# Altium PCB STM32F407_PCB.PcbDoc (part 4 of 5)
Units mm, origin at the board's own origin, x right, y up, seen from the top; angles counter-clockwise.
Board outline 100.27 x 100.27 mm, 2 copper layers (Top Layer, Bottom Layer); 134 components, 132 nets, 659 pads, 288 vias.
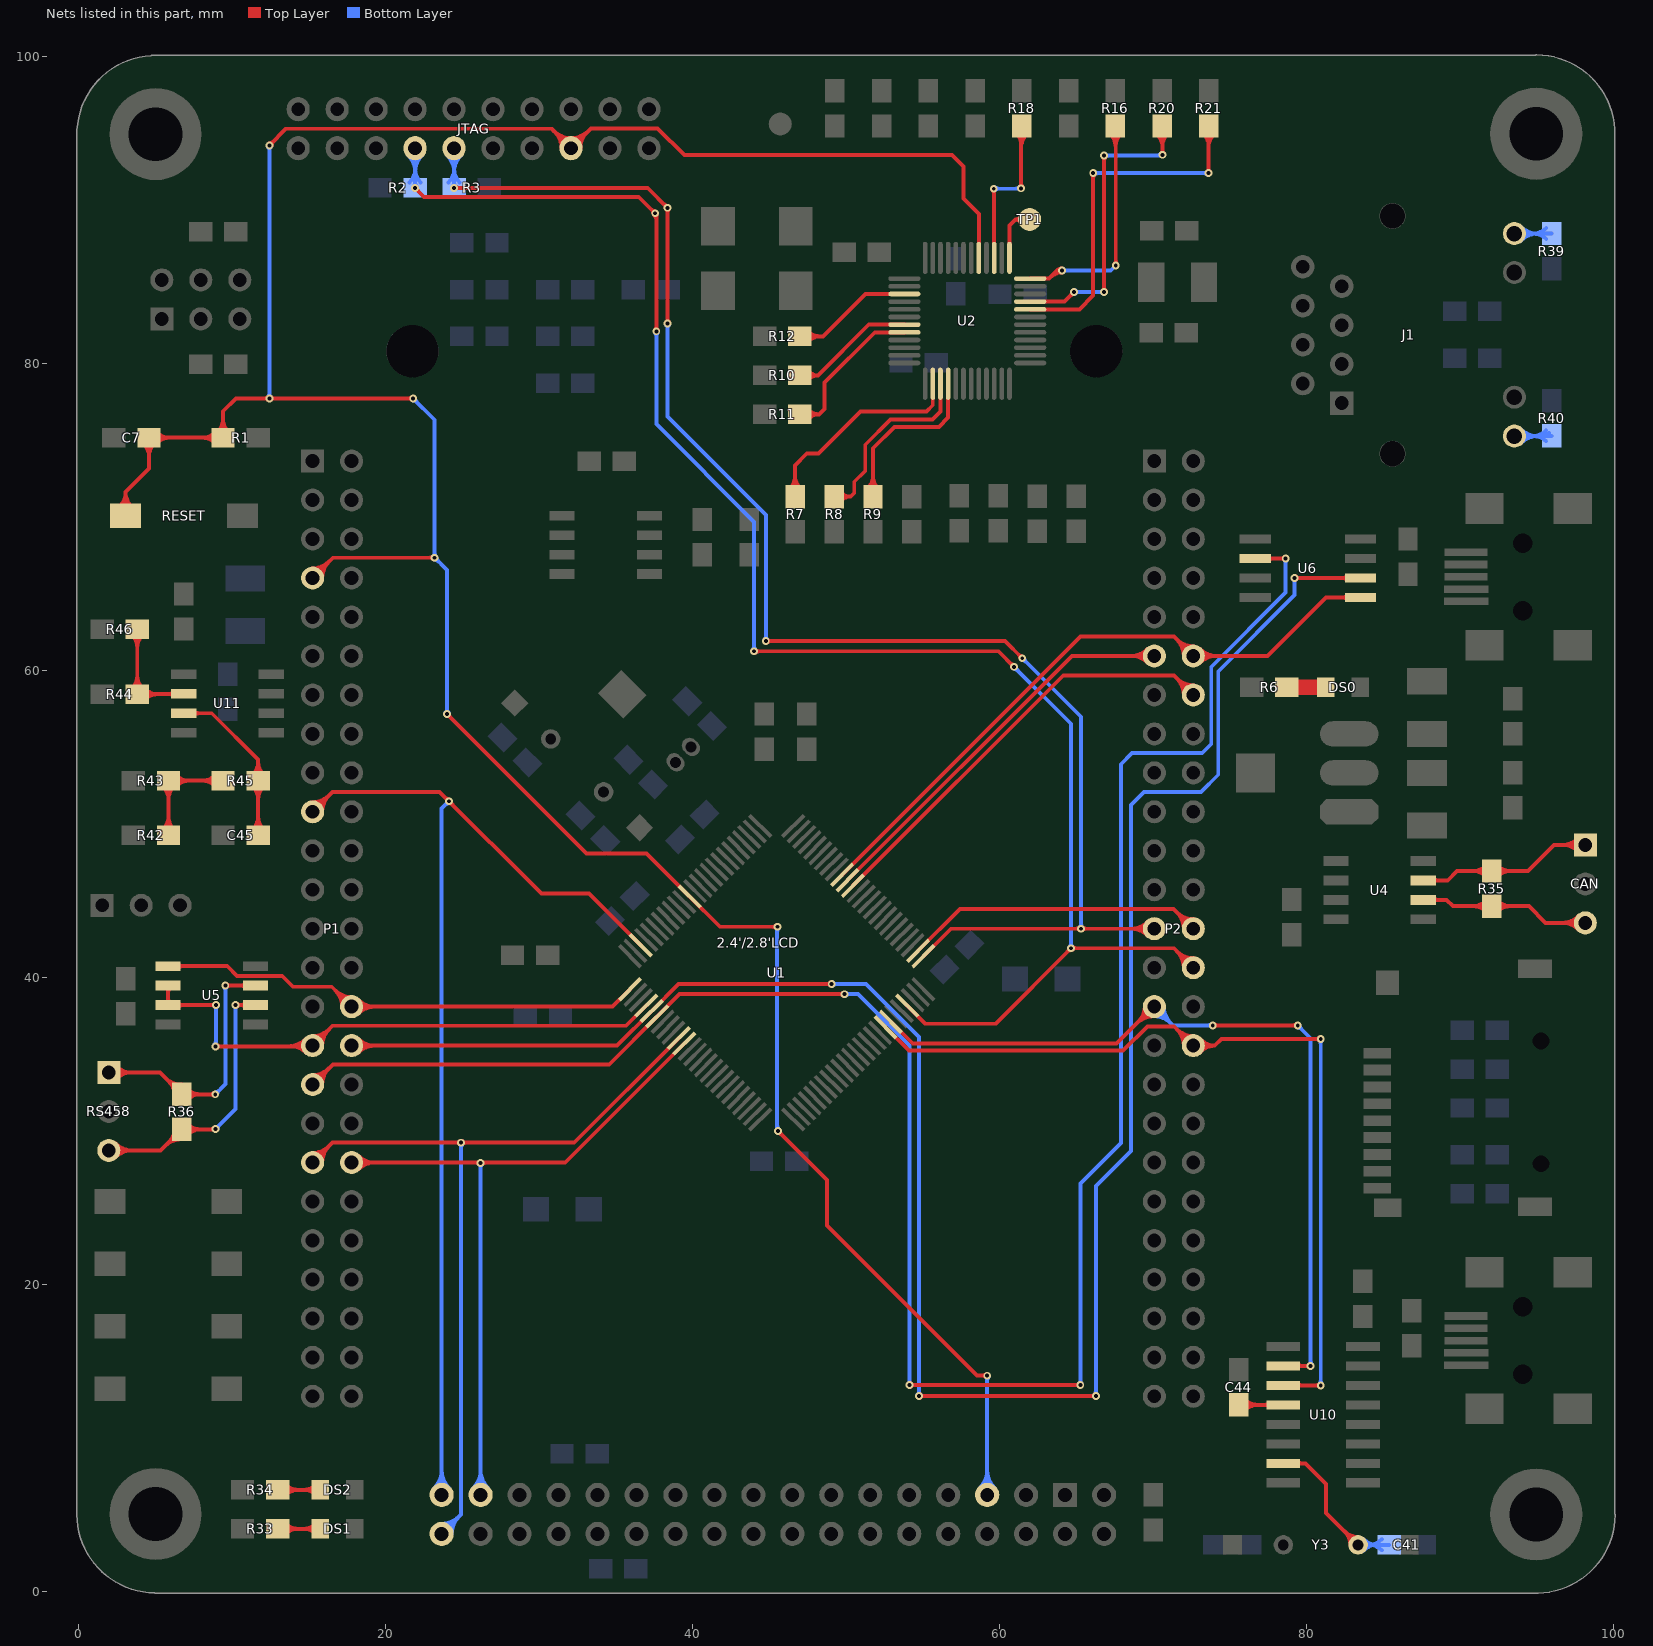
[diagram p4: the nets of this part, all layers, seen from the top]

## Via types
v1: diameter 0.508, hole 0.254, Top Layer to Bottom Layer, 288 vias

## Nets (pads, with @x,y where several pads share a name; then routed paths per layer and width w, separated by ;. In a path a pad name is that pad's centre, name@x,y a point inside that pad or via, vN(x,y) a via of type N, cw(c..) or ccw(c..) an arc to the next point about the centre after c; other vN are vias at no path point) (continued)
NetC41_1: C41.1 U10.7 Y3.1 | length 23.1
  Top Layer w0.254: U10.7@78.502,8.331 79.959,8.331 81.305,6.985 81.305,5.105 Y3.1@83.388,3.023 ; 79.72,8.331 cw(c79.72,8.749) 79.425,8.454 ccw(c79.72,8.749) 79.72,8.331 ; 79.72,8.331 ccw(c79.72,7.914) 79.425,8.209 cw(c79.72,7.914) 79.72,8.331 ; 82.521,3.89 cw(c81.654,3.023) 82.88,3.023 ccw(c81.654,3.023) 82.521,3.89 ; 82.521,3.89 ccw(c83.388,4.757) 83.388,3.531 cw(c83.388,4.757) 82.521,3.89
  Bottom Layer w0.254: Y3.1@83.388,3.023 C41.1@85.419,3.023 ; 84.615,3.023 cw(c84.615,4.249) 83.747,3.382 ccw(c84.615,4.249) 84.615,3.023 ; 84.615,3.023 ccw(c84.615,1.796) 83.747,2.663 cw(c84.615,1.796) 84.615,3.023 ; 84.063,3.023 ccw(c84.063,4.255) 84.934,3.383 cw(c84.063,4.255) 84.063,3.023 ; 84.071,3.023 cw(c84.071,1.802) 84.934,2.665 ccw(c84.071,1.802) 84.071,3.023
NetC44_1: C44.1 U10.4 | length 8
  Top Layer w0.254: C44.1@75.617,12.141 U10.4@78.502,12.141 ; 76.844,12.141 cw(c76.844,13.368) 75.977,12.5 ccw(c76.844,13.368) 76.844,12.141 ; 76.844,12.141 ccw(c76.844,10.915) 75.977,11.782 cw(c76.844,10.915) 76.844,12.141 ; 77.285,12.141 cw(c77.285,11.724) 77.58,12.019 ccw(c77.285,11.724) 77.285,12.141 ; 77.285,12.141 ccw(c77.285,12.559) 77.58,12.264 cw(c77.285,12.559) 77.285,12.141
NetC45_1: C45.1 R45.1 U11.3 | length 24
  Top Layer w0.254: U11.3@6.833,57.226 8.661,57.226 11.684,54.204 R45.1@11.684,52.834 C45.1@11.684,49.278 ; 7.801,57.226 cw(c7.801,57.686) 7.475,57.361 ccw(c7.801,57.686) 7.801,57.226 ; 7.801,57.226 ccw(c7.801,56.766) 7.475,57.091 cw(c7.801,56.766) 7.801,57.226 ; 11.684,50.504 cw(c10.458,50.504) 11.325,49.637 ccw(c10.458,50.504) 11.684,50.504 ; 11.684,50.504 ccw(c12.91,50.504) 12.043,49.637 cw(c12.91,50.504) 11.684,50.504 ; 11.684,51.607 cw(c12.91,51.607) 12.043,52.474 ccw(c12.91,51.607) 11.684,51.607 ; 11.684,51.607 ccw(c10.458,51.607) 11.325,52.474 cw(c10.458,51.607) 11.684,51.607 ; 11.684,54.06 cw(c10.458,54.06) 11.325,53.193 ccw(c10.458,54.06) 11.684,54.06 ; 11.684,54.06 ccw(c12.91,54.06) 12.043,53.193 cw(c12.91,54.06) 11.684,54.06
NetCAN_1: CAN.1 R35.1 U4.7 | length 28.2
  Top Layer w0.254: U4.7@87.64,46.33 89.23,46.33 89.84,46.939 R35.1@92.099,46.939 94.463,46.939 96.164,48.641 CAN.1@98.196,48.641 ; 88.608,46.33 cw(c88.608,46.79) 88.283,46.464 ccw(c88.608,46.79) 88.608,46.33 ; 88.608,46.33 ccw(c88.608,45.87) 88.283,46.195 cw(c88.608,45.87) 88.608,46.33 ; 90.872,46.939 cw(c90.872,45.713) 91.74,46.58 ccw(c90.872,45.713) 90.872,46.939 ; 90.872,46.939 ccw(c90.872,48.166) 91.74,47.298 cw(c90.872,48.166) 90.872,46.939 ; 93.325,46.939 cw(c93.325,48.166) 92.458,47.298 ccw(c93.325,48.166) 93.325,46.939 ; 93.325,46.939 ccw(c93.325,45.713) 92.458,46.58 cw(c93.325,45.713) 93.325,46.939 ; 96.692,48.641 cw(c96.692,47.137) 97.756,48.2 ccw(c96.692,47.137) 96.692,48.641 ; 96.692,48.641 ccw(c96.692,50.145) 97.756,49.082 cw(c96.692,50.145) 96.692,48.641 ; 97.306,48.641 cw(c97.306,47.75) 97.935,48.38 ccw(c97.306,47.75) 97.306,48.641 ; 97.306,48.641 ccw(c97.306,49.532) 97.935,48.902 cw(c97.306,49.532) 97.306,48.641
NetCAN_3: CAN.3 R35.2 U4.6 | length 27.9
  Top Layer w0.254: U4.6@87.64,45.06 89.154,45.06 89.56,44.653 R35.2@92.099,44.653 94.513,44.653 95.606,43.561 CAN.3@98.196,43.561 ; 88.608,45.06 cw(c88.608,45.52) 88.283,45.194 ccw(c88.608,45.52) 88.608,45.06 ; 88.608,45.06 ccw(c88.608,44.6) 88.283,44.925 cw(c88.608,44.6) 88.608,45.06 ; 90.872,44.653 cw(c90.872,43.427) 91.74,44.294 ccw(c90.872,43.427) 90.872,44.653 ; 90.872,44.653 ccw(c90.872,45.88) 91.74,45.012 cw(c90.872,45.88) 90.872,44.653 ; 93.325,44.653 cw(c93.325,45.88) 92.458,45.012 ccw(c93.325,45.88) 93.325,44.653 ; 93.325,44.653 ccw(c93.325,43.427) 92.458,44.294 cw(c93.325,43.427) 93.325,44.653 ; 96.692,43.561 cw(c96.692,42.057) 97.756,43.12 ccw(c96.692,42.057) 96.692,43.561 ; 96.692,43.561 ccw(c96.692,45.065) 97.756,44.002 cw(c96.692,45.065) 96.692,43.561 ; 97.306,43.561 cw(c97.306,42.67) 97.935,43.3 ccw(c97.306,42.67) 97.306,43.561 ; 97.306,43.561 ccw(c97.306,44.452) 97.935,43.822 cw(c97.306,44.452) 97.306,43.561
NetDS0_1: DS0.1 R6.1 | length 2.5
  Top Layer w1.016: R6.1@78.74,58.93 DS0.1@81.278,58.93
NetDS1_1: DS1.1 R33.2 | length 10
  Top Layer w0.254: R33.2@12.954,4.062 DS1.1@15.746,4.062 ; 14.307,4.062 cw(c14.307,5.289) 13.44,4.422 ccw(c14.307,5.289) 14.307,4.062 ; 14.307,4.062 ccw(c14.307,2.836) 13.44,3.703 cw(c14.307,2.836) 14.307,4.062 ; 14.671,4.062 ccw(c14.671,5.141) 15.434,4.378 cw(c14.671,5.141) 14.671,4.062 ; 14.679,4.062 cw(c14.679,2.995) 15.434,3.75 ccw(c14.679,2.995) 14.679,4.062
NetDS2_1: DS2.1 R34.2 | length 10
  Top Layer w0.254: R34.2@12.954,6.602 DS2.1@15.746,6.602 ; 14.307,6.602 cw(c14.307,7.829) 13.44,6.962 ccw(c14.307,7.829) 14.307,6.602 ; 14.307,6.602 ccw(c14.307,5.376) 13.44,6.243 cw(c14.307,5.376) 14.307,6.602 ; 14.671,6.602 ccw(c14.671,7.681) 15.434,6.918 cw(c14.671,7.681) 14.671,6.602 ; 14.679,6.602 cw(c14.679,5.535) 15.434,6.29 ccw(c14.679,5.535) 14.679,6.602
NetJ1_9: J1.9 R40.1 | length 14.9
  Bottom Layer w0.254: J1.9@93.571,75.29 R40.1@95.989,75.29 ; 94.462,75.29 cw(c94.462,76.18) 93.832,75.551 ccw(c94.462,76.18) 94.462,75.29 ; 94.462,75.29 ccw(c94.462,74.399) 93.832,75.029 cw(c94.462,74.399) 94.462,75.29 ; 95.075,75.29 cw(c95.075,76.794) 94.012,75.73 ccw(c95.075,76.794) 95.075,75.29 ; 95.075,75.29 ccw(c95.075,73.786) 94.012,74.849 cw(c95.075,73.786) 95.075,75.29 ; 94.732,75.29 ccw(c94.732,76.589) 95.651,75.67 cw(c94.732,76.589) 94.732,75.29 ; 94.836,75.29 cw(c94.836,74.136) 95.651,74.952 ccw(c94.836,74.136) 94.836,75.29 ; 95.346,75.29 ccw(c95.346,75.976) 95.831,75.491 cw(c95.346,75.976) 95.346,75.29
NetJ1_12: J1.12 R39.2 | length 13.8
  Bottom Layer w0.254: J1.12@93.571,88.49 R39.2@96.006,88.49 ; 94.462,88.49 cw(c94.462,89.38) 93.832,88.751 ccw(c94.462,89.38) 94.462,88.49 ; 94.462,88.49 ccw(c94.462,87.599) 93.832,88.229 cw(c94.462,87.599) 94.462,88.49 ; 95.075,88.49 cw(c95.075,89.994) 94.012,88.93 ccw(c95.075,89.994) 95.075,88.49 ; 95.075,88.49 ccw(c95.075,86.986) 94.012,88.049 cw(c95.075,86.986) 95.075,88.49 ; 94.774,88.49 ccw(c94.774,89.73) 95.651,88.853 cw(c94.774,89.73) 94.774,88.49 ; 94.794,88.49 cw(c94.794,87.277) 95.651,88.134 ccw(c94.794,87.277) 94.794,88.49
NetR7_2: R7.2 U2.2 | length 17.9
  Top Layer w0.254: R7.2@46.685,71.349 46.685,73.383 47.444,74.143 48.209,74.143 50.952,76.886 55.245,76.886 55.662,77.303 U2.2@55.662,78.704 ; 46.685,72.702 cw(c45.459,72.702) 46.326,71.835 ccw(c45.459,72.702) 46.685,72.702 ; 46.685,72.702 ccw(c47.912,72.702) 47.044,71.835 cw(c47.912,72.702) 46.685,72.702
NetR8_2: R8.2 U2.3 | length 15.7
  Top Layer w0.254: R8.2@49.225,71.349 50.317,71.349 ; U2.3@56.162,78.704 56.162,76.888 55.651,76.378 52.908,76.378 51.257,74.727 51.257,73.025 50.546,72.314 50.546,71.577 50.317,71.349 ; 50.317,71.349 cw(c50.317,72.269) 49.614,71.676 ccw(c50.317,72.269) 50.317,71.349 ; 50.317,71.349 ccw(c50.317,70.429) 49.614,71.021 cw(c50.317,70.429) 50.317,71.349
NetR9_2: R9.2 U2.4 | length 14.9
  Top Layer w0.254: R9.2@51.765,71.349 51.765,74.498 53.162,75.895 56.058,75.895 56.662,76.499 U2.4@56.662,78.704 ; 51.765,72.702 cw(c50.539,72.702) 51.406,71.835 ccw(c50.539,72.702) 51.765,72.702 ; 51.765,72.702 ccw(c52.992,72.702) 52.124,71.835 cw(c52.992,72.702) 51.765,72.702
NetR10_2: R10.2 U2.43 | length 11.3
  Top Layer w0.254: R10.2@46.99,79.246 48.182,79.246 ; U2.43@53.812,82.554 51.49,82.554 48.182,79.246 ; 48.182,79.246 cw(c48.182,80.109) 47.512,79.566 ccw(c48.182,80.109) 48.182,79.246 ; 48.182,79.246 ccw(c48.182,78.384) 47.512,78.927 cw(c48.182,78.384) 48.182,79.246
NetR11_2: R11.2 U2.44 | length 13.5
  Top Layer w0.254: R11.2@46.99,76.706 48.258,76.706 ; U2.44@53.812,82.054 51.879,82.054 48.616,78.791 48.616,77.064 48.258,76.706 ; 48.258,76.706 cw(c48.258,77.734) 47.494,77.046 ccw(c48.258,77.734) 48.258,76.706 ; 48.258,76.706 ccw(c48.258,75.678) 47.494,76.366 cw(c48.258,75.678) 48.258,76.706
NetR12_2: R12.2 U2.39 | length 11.8
  Top Layer w0.254: R12.2@46.99,81.786 48.512,81.786 51.28,84.554 U2.39@53.812,84.554 ; 48.343,81.786 cw(c48.343,83.013) 47.476,82.146 ccw(c48.343,83.013) 48.343,81.786 ; 48.343,81.786 ccw(c48.343,80.56) 47.476,81.427 cw(c48.343,80.56) 48.343,81.786
NetR16_2: R16.2 U2.24 | length 24.4
  Top Layer w0.254: U2.24@62.012,85.554 63.227,85.554 63.754,86.081 v1(64.084,86.081) ; R16.2@67.564,95.504 67.589,95.479 v1(67.589,86.411) ; 67.589,86.717 cw(c67.283,86.717) 67.5,86.501 ccw(c67.283,86.717) 67.589,86.717 ; 67.589,86.717 ccw(c67.896,86.717) 67.679,86.501 cw(c67.896,86.717) 67.589,86.717 ; 63.304,85.63 cw(c64.084,84.85) 64.084,85.954 ccw(c64.084,84.85) 63.304,85.63 ; 63.737,86.064 cw(c64.084,85.717) 64.084,86.208 ccw(c64.084,85.717) 63.737,86.064 ; R16.2@67.205,95.018 cw(c66.276,94.089) 67.589,94.089 ccw(c66.276,94.089) R16.2@67.205,95.018 ; R16.2@67.384,95.197 cw(c66.889,94.702) 67.589,94.702 ccw(c66.889,94.702) R16.2@67.384,95.197 ; 67.589,94.212 cw(c68.729,94.212) 67.923,95.018 ccw(c68.729,94.212) 67.589,94.212
  Bottom Layer w0.254: v1(64.084,86.081) 67.259,86.081 v1(67.589,86.411) ; 64.391,86.081 cw(c64.391,86.387) 64.174,86.17 ccw(c64.391,86.387) 64.391,86.081 ; 64.391,86.081 ccw(c64.391,85.774) 64.174,85.991 cw(c64.391,85.774) 64.391,86.081
NetR18_1: R18.1 U2.27 | length 18.6
  Top Layer w0.254: v1(59.639,91.415) 59.662,91.392 U2.27@59.662,86.904 ; v1(61.417,91.44) 61.417,95.452 R18.1@61.47,95.504 ; 61.417,91.747 cw(c61.111,91.747) 61.327,91.53 ccw(c61.111,91.747) 61.417,91.747 ; 61.417,91.747 ccw(c61.724,91.747) 61.507,91.53 cw(c61.724,91.747) 61.417,91.747 ; v1@59.549,91.325 cw(c59.278,91.053) 59.662,91.053 ccw(c59.278,91.053) v1@59.549,91.325 ; R18.1@61.11,95.018 cw(c60.37,94.277) 61.417,94.277 ccw(c60.37,94.277) R18.1@61.11,95.018 ; 61.417,94.024 cw(c62.823,94.024) 61.829,95.018 ccw(c62.823,94.024) 61.417,94.024 ; 61.417,94.637 cw(c62.209,94.637) 61.649,95.197 ccw(c62.209,94.637) 61.417,94.637
  Bottom Layer w0.254: v1(59.639,91.415) 61.392,91.415 v1(61.417,91.44) ; 59.946,91.415 cw(c59.946,91.721) 59.729,91.504 ccw(c59.946,91.721) 59.946,91.415 ; 59.946,91.415 ccw(c59.946,91.108) 59.729,91.325 cw(c59.946,91.108) 59.946,91.415 ; 61.049,91.415 ccw(c61.049,91.808) 61.327,91.53 cw(c61.049,91.808) 61.049,91.415
NetR20_2: R20.2 U2.21 | length 32.1
  Top Layer w0.254: U2.21@62.012,84.054 64.242,84.054 v1(64.872,84.684) ; v1(66.827,84.684) v1(66.827,93.574) ; R20.2@70.612,95.504 70.637,95.479 v1(70.637,93.624) ; 64.655,84.467 cw(c64.872,84.25) 64.872,84.557 ccw(c64.872,84.25) 64.655,84.467 ; 64.655,84.467 ccw(c64.438,84.684) 64.745,84.684 cw(c64.438,84.684) 64.655,84.467 ; 66.827,84.99 cw(c66.521,84.99) 66.738,84.773 ccw(c66.521,84.99) 66.827,84.99 ; 66.827,84.99 ccw(c67.134,84.99) 66.917,84.773 cw(c67.134,84.99) 66.827,84.99 ; 66.827,93.267 cw(c67.134,93.267) 66.917,93.484 ccw(c67.134,93.267) 66.827,93.267 ; 66.827,93.267 ccw(c66.521,93.267) 66.738,93.484 cw(c66.521,93.267) 66.827,93.267 ; 70.637,93.931 cw(c70.331,93.931) 70.548,93.714 ccw(c70.331,93.931) 70.637,93.931 ; 70.637,93.931 ccw(c70.944,93.931) 70.727,93.714 cw(c70.944,93.931) 70.637,93.931 ; R20.2@70.253,95.018 cw(c69.324,94.089) 70.637,94.089 ccw(c69.324,94.089) R20.2@70.253,95.018 ; R20.2@70.432,95.197 cw(c69.937,94.702) 70.637,94.702 ccw(c69.937,94.702) R20.2@70.432,95.197 ; 70.637,94.212 cw(c71.777,94.212) 70.971,95.018 ccw(c71.777,94.212) 70.637,94.212
  Bottom Layer w0.254: v1(64.872,84.684) v1(66.827,84.684) ; v1(66.827,93.574) 70.587,93.574 v1(70.637,93.624) ; 65.178,84.684 cw(c65.178,84.99) 64.961,84.773 ccw(c65.178,84.99) 65.178,84.684 ; 65.178,84.684 ccw(c65.178,84.377) 64.961,84.594 cw(c65.178,84.377) 65.178,84.684 ; 66.521,84.684 cw(c66.521,84.377) 66.738,84.594 ccw(c66.521,84.377) 66.521,84.684 ; 66.521,84.684 ccw(c66.521,84.99) 66.738,84.773 cw(c66.521,84.99) 66.521,84.684 ; 67.134,93.574 cw(c67.134,93.88) 66.917,93.663 ccw(c67.134,93.88) 67.134,93.574 ; 67.134,93.574 ccw(c67.134,93.267) 66.917,93.484 cw(c67.134,93.267) 67.134,93.574 ; 70.208,93.574 ccw(c70.208,94.054) 70.548,93.714 cw(c70.208,94.054) 70.208,93.574
NetR21_2: R21.2 U2.20 | length 31.9
  Top Layer w0.254: U2.20@62.012,83.554 65.215,83.554 66.116,84.455 v1(66.116,92.431) ; v1(73.635,92.431) 73.635,95.479 R21.2@73.66,95.504 ; 66.116,92.124 cw(c66.423,92.124) 66.206,92.341 ccw(c66.423,92.124) 66.116,92.124 ; 66.116,92.124 ccw(c65.81,92.124) 66.026,92.341 cw(c65.81,92.124) 66.116,92.124 ; 73.635,92.737 cw(c73.328,92.737) 73.545,92.52 ccw(c73.328,92.737) 73.635,92.737 ; 73.635,92.737 ccw(c73.941,92.737) 73.724,92.52 cw(c73.941,92.737) 73.635,92.737 ; R21.2@73.301,95.018 cw(c72.495,94.212) 73.635,94.212 ccw(c72.495,94.212) R21.2@73.301,95.018 ; 73.635,94.089 cw(c74.948,94.089) 74.019,95.018 ccw(c74.948,94.089) 73.635,94.089 ; 73.635,94.702 cw(c74.335,94.702) 73.84,95.197 ccw(c74.335,94.702) 73.635,94.702
  Bottom Layer w0.254: v1(66.116,92.431) v1(73.635,92.431) ; 66.423,92.431 cw(c66.423,92.737) 66.206,92.52 ccw(c66.423,92.737) 66.423,92.431 ; 66.423,92.431 ccw(c66.423,92.124) 66.206,92.341 cw(c66.423,92.124) 66.423,92.431 ; 73.328,92.431 cw(c73.328,92.124) 73.545,92.341 ccw(c73.328,92.124) 73.328,92.431 ; 73.328,92.431 ccw(c73.328,92.737) 73.545,92.52 cw(c73.328,92.737) 73.328,92.431
NetR36_1: R36.1 RS458.1 U5.7 | length 38.8
  Top Layer w0.254: RS458.1@1.956,33.807 5.282,33.807 R36.1@6.704,32.385 v1(8.89,32.385) ; v1(9.55,39.472) U5.7@11.517,39.472 ; 2.847,33.807 cw(c2.847,34.698) 2.217,34.068 ccw(c2.847,34.698) 2.847,33.807 ; 2.847,33.807 ccw(c2.847,32.917) 2.217,33.546 cw(c2.847,32.917) 2.847,33.807 ; 3.46,33.807 cw(c3.46,35.311) 2.396,34.248 ccw(c3.46,35.311) 3.46,33.807 ; 3.46,33.807 ccw(c3.46,32.303) 2.396,33.367 cw(c3.46,32.303) 3.46,33.807 ; 7.93,32.385 cw(c7.93,33.611) 7.063,32.744 ccw(c7.93,33.611) 7.93,32.385 ; 7.93,32.385 ccw(c7.93,31.159) 7.063,32.026 cw(c7.93,31.159) 7.93,32.385 ; 8.583,32.385 cw(c8.583,32.078) 8.8,32.295 ccw(c8.583,32.078) 8.583,32.385 ; 8.583,32.385 ccw(c8.583,32.692) 8.8,32.475 cw(c8.583,32.692) 8.583,32.385 ; 9.857,39.472 cw(c9.857,39.778) 9.64,39.561 ccw(c9.857,39.778) 9.857,39.472 ; 9.857,39.472 ccw(c9.857,39.165) 9.64,39.382 cw(c9.857,39.165) 9.857,39.472 ; 10.549,39.472 cw(c10.549,39.012) 10.874,39.337 ccw(c10.549,39.012) 10.549,39.472 ; 10.549,39.472 ccw(c10.549,39.932) 10.874,39.606 cw(c10.549,39.932) 10.549,39.472 ; 5.62,33.469 ccw(c6.704,34.553) 6.704,33.02 cw(c6.704,34.553) 5.62,33.469 ; 5.927,33.162 cw(c5.276,32.512) 6.196,32.512 ccw(c5.276,32.512) 5.927,33.162 ; 6.054,33.035 ccw(c6.704,33.686) 6.704,32.766 cw(c6.704,33.686) 6.054,33.035
  Bottom Layer w0.254: v1(8.89,32.385) 9.55,33.045 v1(9.55,39.472) ; 9.107,32.602 cw(c8.89,32.819) 8.89,32.512 ccw(c8.89,32.819) 9.107,32.602 ; 9.107,32.602 ccw(c9.324,32.385) 9.017,32.385 cw(c9.324,32.385) 9.107,32.602 ; 9.55,39.165 cw(c9.857,39.165) 9.64,39.382 ccw(c9.857,39.165) 9.55,39.165 ; 9.55,39.165 ccw(c9.244,39.165) 9.461,39.382 cw(c9.244,39.165) 9.55,39.165
NetR36_2: R36.2 RS458.3 U5.6 | length 39.1
  Top Layer w0.254: RS458.3@1.956,28.727 5.332,28.727 R36.2@6.704,30.099 8.89,30.099 v1(8.915,30.124) ; v1(10.211,38.202) U5.6@11.517,38.202 ; 2.847,28.727 cw(c2.847,29.618) 2.217,28.988 ccw(c2.847,29.618) 2.847,28.727 ; 2.847,28.727 ccw(c2.847,27.837) 2.217,28.466 cw(c2.847,27.837) 2.847,28.727 ; 3.46,28.727 cw(c3.46,30.231) 2.396,29.168 ccw(c3.46,30.231) 3.46,28.727 ; 3.46,28.727 ccw(c3.46,27.223) 2.396,28.287 cw(c3.46,27.223) 3.46,28.727 ; 7.93,30.099 cw(c7.93,31.325) 7.063,30.458 ccw(c7.93,31.325) 7.93,30.099 ; 7.93,30.099 ccw(c7.93,28.873) 7.063,29.74 cw(c7.93,28.873) 7.93,30.099 ; 10.517,38.202 cw(c10.517,38.508) 10.301,38.291 ccw(c10.517,38.508) 10.517,38.202 ; 10.517,38.202 ccw(c10.517,37.895) 10.301,38.112 cw(c10.517,37.895) 10.517,38.202 ; 10.549,38.202 cw(c10.549,37.742) 10.874,38.067 ccw(c10.549,37.742) 10.549,38.202 ; 10.549,38.202 ccw(c10.549,38.662) 10.874,38.336 cw(c10.549,38.662) 10.549,38.202 ; 5.62,29.015 cw(c6.704,27.931) 6.704,29.464 ccw(c6.704,27.931) 5.62,29.015 ; 5.927,29.322 ccw(c5.276,29.972) 6.196,29.972 cw(c5.276,29.972) 5.927,29.322 ; 6.054,29.449 cw(c6.704,28.798) 6.704,29.718 ccw(c6.704,28.798) 6.054,29.449 ; 8.547,30.099 ccw(c8.547,30.492) 8.826,30.214 cw(c8.547,30.492) 8.547,30.099
  Bottom Layer w0.254: v1(8.915,30.124) 10.211,31.42 v1(10.211,38.202) ; 9.132,30.341 cw(c8.915,30.558) 8.915,30.251 ccw(c8.915,30.558) 9.132,30.341 ; 9.132,30.341 ccw(c9.349,30.124) 9.042,30.124 cw(c9.349,30.124) 9.132,30.341 ; 10.211,37.895 cw(c10.517,37.895) 10.301,38.112 ccw(c10.517,37.895) 10.211,37.895 ; 10.211,37.895 ccw(c9.904,37.895) 10.121,38.112 cw(c9.904,37.895) 10.211,37.895
NetR42_2: R42.2 R43.2 R45.2 | length 22.5
  Top Layer w0.254: R42.2@5.842,49.274 R43.2@5.842,52.83 R45.2@9.395,52.83 ; 5.842,50.501 cw(c4.616,50.501) 5.483,49.634 ccw(c4.616,50.501) 5.842,50.501 ; 5.842,50.501 ccw(c7.068,50.501) 6.201,49.634 cw(c7.068,50.501) 5.842,50.501 ; 5.842,51.604 cw(c7.068,51.604) 6.201,52.471 ccw(c7.068,51.604) 5.842,51.604 ; 5.842,51.604 ccw(c4.616,51.604) 5.483,52.471 cw(c4.616,51.604) 5.842,51.604 ; 7.195,52.83 cw(c7.195,54.057) 6.328,53.19 ccw(c7.195,54.057) 7.195,52.83 ; 7.195,52.83 ccw(c7.195,51.604) 6.328,52.471 cw(c7.195,51.604) 7.195,52.83 ; 8.037,52.83 ccw(c8.037,54.068) 8.912,53.193 cw(c8.037,54.068) 8.037,52.83 ; 8.052,52.83 cw(c8.052,51.615) 8.912,52.474 ccw(c8.052,51.615) 8.052,52.83
NetR44_2: R44.2 R46.2 U11.2 | length 20.2
  Top Layer w0.254: R46.2@3.81,62.711 R44.2@3.81,58.469 U11.2@6.806,58.469 ; 3.81,59.696 cw(c2.584,59.696) 3.451,58.828 ccw(c2.584,59.696) 3.81,59.696 ; 3.81,59.696 ccw(c5.036,59.696) 4.169,58.828 cw(c5.036,59.696) 3.81,59.696 ; 3.81,61.485 cw(c5.036,61.485) 4.169,62.352 ccw(c5.036,61.485) 3.81,61.485 ; 3.81,61.485 ccw(c2.584,61.485) 3.451,62.352 cw(c2.584,61.485) 3.81,61.485 ; 5.163,58.469 cw(c5.163,59.696) 4.296,58.828 ccw(c5.163,59.696) 5.163,58.469 ; 5.163,58.469 ccw(c5.163,57.243) 4.296,58.11 cw(c5.163,57.243) 5.163,58.469 ; 5.799,58.469 ccw(c5.799,59.021) 6.19,58.631 cw(c5.799,59.021) 5.799,58.469 ; 5.93,58.469 cw(c5.93,58.102) 6.19,58.361 ccw(c5.93,58.102) 5.93,58.469
NetTP1_1: TP1.1 U2.25 | length 5.3
  Top Layer w0.254: U2.25@60.662,86.904 60.662,89.008 61.062,89.408 ; TP1.1@61.976,89.408 61.062,89.408 ; 61.062,89.408 cw(c61.062,89.049) 61.396,89.18 ccw(c61.062,89.049) 61.062,89.408 ; 61.062,89.408 ccw(c61.062,89.767) 61.396,89.636 cw(c61.062,89.767) 61.062,89.408
NRST: 2.4'/2.8'LCD.5 C7.1 JTAG.15 P1.7 R1.2 RESET.1 U1.14 U2.29 | length 266.6
  Top Layer w0.254: RESET.1@3.048,70.104 3.048,71.653 ; v1(12.421,94.234) 13.513,95.326 30.81,95.326 JTAG.15@32.08,94.056 33.376,95.352 37.719,95.352 39.472,93.599 56.921,93.599 57.658,92.862 57.658,90.78 58.662,89.776 U2.29@58.662,86.904 ; P1.7@15.24,66.04 16.561,67.361 v1(23.19,67.361) ; v1(21.793,77.749) v1(12.421,77.749) 10.236,77.749 9.398,76.911 R1.2@9.398,75.186 C7.1@4.572,75.186 4.572,73.177 3.048,71.653 ; v1(24.003,57.175) 33.096,48.082 37.012,48.082 U1.14@39.817,45.277 41.787,43.307 v1(45.542,43.307) ; v1(45.568,29.997) 48.768,26.797 48.768,23.825 58.547,14.046 v1(59.207,14.046) ; 3.048,71.069 cw(c2.147,71.069) 2.762,70.41 ccw(c2.147,71.069) 3.048,71.069 ; 3.048,71.069 ccw(c3.949,71.069) 3.334,70.41 cw(c3.949,71.069) 3.048,71.069 ; 3.048,71.653 cw(c1.601,71.653) 2.589,70.596 ccw(c1.601,71.653) 3.048,71.653 ; 3.048,71.653 ccw(c4.495,71.653) 3.507,70.596 cw(c4.495,71.653) 3.048,71.653 ; 4.572,73.959 cw(c5.798,73.959) 4.931,74.826 ccw(c5.798,73.959) 4.572,73.959 ; 4.572,73.959 ccw(c3.346,73.959) 4.213,74.826 cw(c3.346,73.959) 4.572,73.959 ; 5.925,75.186 cw(c5.925,76.412) 5.058,75.545 ccw(c5.925,76.412) 5.925,75.186 ; 5.925,75.186 ccw(c5.925,73.959) 5.058,74.826 cw(c5.925,73.959) 5.925,75.186 ; 8.045,75.186 cw(c8.045,73.959) 8.912,74.826 ccw(c8.045,73.959) 8.045,75.186 ; 8.045,75.186 ccw(c8.045,76.412) 8.912,75.545 cw(c8.045,76.412) 8.045,75.186 ; 9.398,76.412 cw(c8.172,76.412) 9.039,75.545 ccw(c8.172,76.412) 9.398,76.412 ; 9.398,76.412 ccw(c10.624,76.412) 9.757,75.545 cw(c10.624,76.412) 9.398,76.412 ; 12.114,77.749 cw(c12.114,77.443) 12.331,77.66 ccw(c12.114,77.443) 12.114,77.749 ; 12.114,77.749 ccw(c12.114,78.056) 12.331,77.839 cw(c12.114,78.056) 12.114,77.749 ; 12.637,94.451 cw(c12.421,94.668) 12.421,94.361 ccw(c12.421,94.668) 12.637,94.451 ; 12.637,94.451 ccw(c12.854,94.234) 12.548,94.234 cw(c12.854,94.234) 12.637,94.451 ; 12.727,77.749 cw(c12.727,78.056) 12.51,77.839 ccw(c12.727,78.056) 12.727,77.749 ; 12.727,77.749 ccw(c12.727,77.443) 12.51,77.66 cw(c12.727,77.443) 12.727,77.749 ; 15.87,66.67 cw(c15.24,67.3) 15.24,66.409 ccw(c15.24,67.3) 15.87,66.67 ; 15.87,66.67 ccw(c16.5,66.04) 15.609,66.04 cw(c16.5,66.04) 15.87,66.67 ; 16.304,67.104 cw(c15.24,68.167) 15.24,66.663 ccw(c15.24,68.167) 16.304,67.104 ; 16.304,67.104 ccw(c17.367,66.04) 15.863,66.04 cw(c17.367,66.04) 16.304,67.104 ; 21.487,77.749 cw(c21.487,77.443) 21.703,77.66 ccw(c21.487,77.443) 21.487,77.749 ; 21.487,77.749 ccw(c21.487,78.056) 21.703,77.839 cw(c21.487,78.056) 21.487,77.749 ; 22.884,67.361 cw(c22.884,67.054) 23.1,67.271 ccw(c22.884,67.054) 22.884,67.361 ; 22.884,67.361 ccw(c22.884,67.667) 23.1,67.451 cw(c22.884,67.667) 22.884,67.361 ; 24.22,56.959 cw(c24.437,57.175) 24.13,57.175 ccw(c24.437,57.175) 24.22,56.959 ; 24.22,56.959 ccw(c24.003,56.742) 24.003,57.048 cw(c24.003,56.742) 24.22,56.959 ; JTAG.15@32.08,94.463 cw(c32.08,95.444) 31.386,94.75 ccw(c32.08,95.444) JTAG.15@32.08,94.463 ; JTAG.15@32.08,94.463 ccw(c32.08,95.444) 32.774,94.75 cw(c32.08,95.444) JTAG.15@32.08,94.463 ; JTAG.15@32.08,94.717 cw(c32.08,96.311) 30.953,95.184 ccw(c32.08,96.311) JTAG.15@32.08,94.717 ; JTAG.15@32.08,94.717 ccw(c32.08,96.311) 33.208,95.184 cw(c32.08,96.311) JTAG.15@32.08,94.717 ; 45.236,43.307 cw(c45.236,43) 45.452,43.217 ccw(c45.236,43) 45.236,43.307 ; 45.236,43.307 ccw(c45.236,43.614) 45.452,43.397 cw(c45.236,43.614) 45.236,43.307 ; 45.784,29.781 cw(c46.001,29.997) 45.695,29.997 ccw(c46.001,29.997) 45.784,29.781 ; 45.784,29.781 ccw(c45.568,29.564) 45.568,29.87 cw(c45.568,29.564) 45.784,29.781 ; 58.901,14.046 cw(c58.901,13.74) 59.118,13.956 ccw(c58.901,13.74) 58.901,14.046 ; 58.901,14.046 ccw(c58.901,14.353) 59.118,14.136 cw(c58.901,14.353) 58.901,14.046 ; 31.043,95.093 cw(c30.043,94.094) 31.457,94.094 ccw(c30.043,94.094) 31.043,95.093 ; 31.477,94.66 cw(c30.911,94.094) 31.711,94.094 ccw(c30.911,94.094) 31.477,94.66 ; JTAG.15@32.449,94.094 cw(c33.25,94.094) 32.684,94.66 ccw(c33.25,94.094) JTAG.15@32.449,94.094 ; JTAG.15@32.703,94.094 cw(c34.117,94.094) 33.117,95.093 ccw(c34.117,94.094) JTAG.15@32.703,94.094
  Bottom Layer w0.254: v1(12.421,77.749) v1(12.421,94.234) ; v1(21.793,77.749) 23.19,76.352 v1(23.19,67.361) ; v1@23.216,67.361 24.003,66.573 v1(24.003,57.175) ; v1@45.517,43.332 45.517,30.048 v1(45.568,29.997) ; 2.4'/2.8'LCD.5@59.207,6.274 v1(59.207,14.046) ; 12.421,78.056 cw(c12.114,78.056) 12.331,77.839 ccw(c12.114,78.056) 12.421,78.056 ; 12.421,78.056 ccw(c12.727,78.056) 12.51,77.839 cw(c12.727,78.056) 12.421,78.056 ; 12.421,93.927 cw(c12.727,93.927) 12.51,94.144 ccw(c12.727,93.927) 12.421,93.927 ; 12.421,93.927 ccw(c12.114,93.927) 12.331,94.144 cw(c12.114,93.927) 12.421,93.927 ; 22.01,77.533 cw(c22.227,77.749) 21.92,77.749 ccw(c22.227,77.749) 22.01,77.533 ; 22.01,77.533 ccw(c21.793,77.316) 21.793,77.622 cw(c21.793,77.316) 22.01,77.533 ; 23.19,67.667 cw(c22.884,67.667) 23.1,67.451 ccw(c22.884,67.667) 23.19,67.667 ; 23.19,67.667 ccw(c23.497,67.667) 23.28,67.451 cw(c23.497,67.667) 23.19,67.667 ; 24.003,57.482 cw(c23.696,57.482) 23.913,57.265 ccw(c23.696,57.482) 24.003,57.482 ; 24.003,57.482 ccw(c24.31,57.482) 24.093,57.265 cw(c24.31,57.482) 24.003,57.482 ; 59.207,7.255 cw(c58.226,7.255) 58.92,6.561 ccw(c58.226,7.255) 59.207,7.255 ; 59.207,7.255 ccw(c60.189,7.255) 59.495,6.561 cw(c60.189,7.255) 59.207,7.255 ; 59.207,7.868 cw(c57.613,7.868) 58.74,6.741 ccw(c57.613,7.868) 59.207,7.868 ; 59.207,7.868 ccw(c60.802,7.868) 59.674,6.741 cw(c60.802,7.868) 59.207,7.868 ; 59.207,13.74 cw(c59.514,13.74) 59.297,13.956 ccw(c59.514,13.74) 59.207,13.74 ; 59.207,13.74 ccw(c58.901,13.74) 59.118,13.956 cw(c58.901,13.74) 59.207,13.74 ; v1@23.19,67.234 cw(c23.19,66.866) 23.45,67.126 ccw(c23.19,66.866) v1@23.19,67.234 ; v1@23.317,67.361 ccw(c23.562,67.361) 23.389,67.187 cw(c23.562,67.361) v1@23.317,67.361 ; 45.517,30.427 ccw(c45.997,30.427) 45.657,30.087 cw(c45.997,30.427) 45.517,30.427 ; 45.517,42.939 cw(c45.91,42.939) 45.632,43.217 ccw(c45.91,42.939) 45.517,42.939
PA0: 2.4'/2.8'LCD.33 P1.19 U1.23 | length 90
  Top Layer w0.254: P1.19@15.24,50.8 16.535,52.095 23.52,52.095 30.15,45.466 33.264,45.466 U1.23@36.635,42.095 ; 15.87,51.43 cw(c15.24,52.06) 15.24,51.169 ccw(c15.24,52.06) 15.87,51.43 ; 15.87,51.43 ccw(c16.5,50.8) 15.609,50.8 cw(c16.5,50.8) 15.87,51.43 ; 16.304,51.864 cw(c15.24,52.927) 15.24,51.423 ccw(c15.24,52.927) 16.304,51.864 ; 16.304,51.864 ccw(c17.367,50.8) 15.863,50.8 cw(c17.367,50.8) 16.304,51.864 ; 23.913,51.703 cw(c23.696,51.486) 24.003,51.486 ccw(c23.696,51.486) 23.913,51.703 ; 23.913,51.703 ccw(c24.13,51.919) 24.13,51.613 cw(c24.13,51.919) 23.913,51.703 ; 24.347,51.269 cw(c24.564,51.486) 24.257,51.486 ccw(c24.564,51.486) 24.347,51.269 ; 24.347,51.269 ccw(c24.13,51.052) 24.13,51.359 cw(c24.13,51.052) 24.347,51.269
  Bottom Layer w0.254: 2.4'/2.8'LCD.33@23.647,6.274 23.647,51.003 v1(24.13,51.486) ; 23.647,7.255 cw(c22.666,7.255) 23.36,6.561 ccw(c22.666,7.255) 23.647,7.255 ; 23.647,7.255 ccw(c24.629,7.255) 23.935,6.561 cw(c24.629,7.255) 23.647,7.255 ; 23.647,7.868 cw(c22.053,7.868) 23.18,6.741 ccw(c22.053,7.868) 23.647,7.868 ; 23.647,7.868 ccw(c25.242,7.868) 24.114,6.741 cw(c25.242,7.868) 23.647,7.868 ; 23.913,51.269 cw(c24.13,51.052) 24.13,51.359 ccw(c24.13,51.052) 23.913,51.269 ; 23.913,51.269 ccw(c23.696,51.486) 24.003,51.486 cw(c23.696,51.486) 23.913,51.269
PA3: P1.30 U1.26 U5.1 | length 48.2
  Top Layer w0.254: U5.1@5.817,40.742 9.677,40.742 10.312,40.107 13.259,40.107 13.97,39.395 16.485,39.395 P1.30@17.78,38.1 34.796,38.1 U1.26@35.928,39.231 ; 6.785,40.742 cw(c6.785,41.202) 6.459,40.876 ccw(c6.785,41.202) 6.785,40.742 ; 6.785,40.742 ccw(c6.785,40.282) 6.459,40.607 cw(c6.785,40.282) 6.785,40.742 ; 16.716,39.164 cw(c15.653,38.1) 17.157,38.1 ccw(c15.653,38.1) 16.716,39.164 ; 16.716,39.164 ccw(c17.78,40.227) 17.78,38.723 cw(c17.78,40.227) 16.716,39.164 ; 17.15,38.73 cw(c16.52,38.1) 17.411,38.1 ccw(c16.52,38.1) 17.15,38.73 ; 17.15,38.73 ccw(c17.78,39.36) 17.78,38.469 cw(c17.78,39.36) 17.15,38.73 ; 18.671,38.1 cw(c18.671,38.991) 18.041,38.361 ccw(c18.671,38.991) 18.671,38.1 ; 18.671,38.1 ccw(c18.671,37.209) 18.041,37.839 cw(c18.671,37.209) 18.671,38.1 ; 19.284,38.1 cw(c19.284,39.604) 18.221,38.541 ccw(c19.284,39.604) 19.284,38.1 ; 19.284,38.1 ccw(c19.284,36.596) 18.221,37.659 cw(c19.284,36.596) 19.284,38.1
PA4: P1.31 U1.29 U5.2 U5.3 | length 59.1
  Top Layer w0.254: U5.2@5.817,39.472 U5.3@5.817,38.202 v1(8.941,38.202) ; v1(8.915,35.509) P1.31@15.189,35.509 ; P1.31@15.24,35.56 16.535,36.855 35.673,36.855 U1.29@36.988,38.171 ; 5.817,38.662 cw(c5.357,38.662) 5.682,38.336 ccw(c5.357,38.662) 5.817,38.662 ; 5.817,38.662 ccw(c6.277,38.662) 5.951,38.336 cw(c6.277,38.662) 5.817,38.662 ; 5.817,39.012 cw(c6.277,39.012) 5.951,39.337 ccw(c6.277,39.012) 5.817,39.012 ; 5.817,39.012 ccw(c5.357,39.012) 5.682,39.337 cw(c5.357,39.012) 5.817,39.012 ; 6.785,38.202 cw(c6.785,38.662) 6.459,38.336 ccw(c6.785,38.662) 6.785,38.202 ; 6.785,38.202 ccw(c6.785,37.742) 6.459,38.067 cw(c6.785,37.742) 6.785,38.202 ; 8.634,38.202 cw(c8.634,37.895) 8.851,38.112 ccw(c8.634,37.895) 8.634,38.202 ; 8.634,38.202 ccw(c8.634,38.508) 8.851,38.291 cw(c8.634,38.508) 8.634,38.202 ; 9.222,35.509 cw(c9.222,35.816) 9.005,35.599 ccw(c9.222,35.816) 9.222,35.509 ; 9.222,35.509 ccw(c9.222,35.203) 9.005,35.419 cw(c9.222,35.203) 9.222,35.509 ; 15.87,36.19 cw(c15.24,36.82) 15.24,35.929 ccw(c15.24,36.82) 15.87,36.19 ; 15.87,36.19 ccw(c16.5,35.56) 15.609,35.56 cw(c16.5,35.56) 15.87,36.19 ; 16.304,36.624 cw(c15.24,37.687) 15.24,36.183 ccw(c15.24,37.687) 16.304,36.624 ; 16.304,36.624 ccw(c17.367,35.56) 15.863,35.56 cw(c17.367,35.56) 16.304,36.624 ; 13.613,35.509 ccw(c13.613,37.187) 14.799,36.001 cw(c13.613,37.187) 13.613,35.509 ; 13.859,35.509 cw(c13.859,34.179) 14.799,35.119 ccw(c13.859,34.179) 13.859,35.509 ; 14.227,35.509 ccw(c14.227,36.573) 14.979,35.821 cw(c14.227,36.573) 14.227,35.509 ; 14.472,35.509 cw(c14.472,34.792) 14.979,35.299 ccw(c14.472,34.792) 14.472,35.509
  Bottom Layer w0.254: v1(8.915,35.509) 8.941,35.535 v1(8.941,38.202) ; 8.941,37.895 cw(c9.247,37.895) 9.031,38.112 ccw(c9.247,37.895) 8.941,37.895 ; 8.941,37.895 ccw(c8.634,37.895) 8.851,38.112 cw(c8.634,37.895) 8.941,37.895 ; v1@8.826,35.599 ccw(c8.547,35.877) 8.941,35.877 cw(c8.547,35.877) v1@8.826,35.599
PA5: P1.32 U1.30 U6.6 | length 156.7
  Top Layer w0.254: P1.32@17.78,35.56 35.085,35.56 U1.30@37.342,37.817 39.098,39.573 v1(49.073,39.573) ; v1(54.762,12.725) v1(66.294,12.725) ; v1(79.248,66.04) U6.6@83.541,66.04 ; 18.671,35.56 cw(c18.671,36.451) 18.041,35.821 ccw(c18.671,36.451) 18.671,35.56 ; 18.671,35.56 ccw(c18.671,34.669) 18.041,35.299 cw(c18.671,34.669) 18.671,35.56 ; 19.284,35.56 cw(c19.284,37.064) 18.221,36.001 ccw(c19.284,37.064) 19.284,35.56 ; 19.284,35.56 ccw(c19.284,34.056) 18.221,35.119 cw(c19.284,34.056) 19.284,35.56 ; 48.766,39.573 cw(c48.766,39.267) 48.983,39.483 ccw(c48.766,39.267) 48.766,39.573 ; 48.766,39.573 ccw(c48.766,39.88) 48.983,39.663 cw(c48.766,39.88) 48.766,39.573 ; 55.069,12.725 cw(c55.069,13.032) 54.852,12.815 ccw(c55.069,13.032) 55.069,12.725 ; 55.069,12.725 ccw(c55.069,12.419) 54.852,12.636 cw(c55.069,12.419) 55.069,12.725 ; 65.987,12.725 cw(c65.987,12.419) 66.204,12.636 ccw(c65.987,12.419) 65.987,12.725 ; 65.987,12.725 ccw(c65.987,13.032) 66.204,12.815 cw(c65.987,13.032) 65.987,12.725 ; 79.555,66.04 cw(c79.555,66.347) 79.338,66.13 ccw(c79.555,66.347) 79.555,66.04 ; 79.555,66.04 ccw(c79.555,65.733) 79.338,65.95 cw(c79.555,65.733) 79.555,66.04 ; 82.4,66.04 cw(c82.4,65.611) 82.704,65.914 ccw(c82.4,65.611) 82.4,66.04 ; 82.4,66.04 ccw(c82.4,66.469) 82.704,66.166 cw(c82.4,66.469) 82.4,66.04
  Bottom Layer w0.254: v1(49.073,39.573) 51.308,39.573 54.762,36.119 v1(54.762,12.725) ; v1(66.294,12.725) 66.294,26.416 68.58,28.702 68.58,51.246 69.43,52.095 73.152,52.095 74.27,53.213 74.27,59.944 79.248,64.922 v1(79.248,66.04) ; 49.379,39.573 cw(c49.379,39.88) 49.163,39.663 ccw(c49.379,39.88) 49.379,39.573 ; 49.379,39.573 ccw(c49.379,39.267) 49.163,39.483 cw(c49.379,39.267) 49.379,39.573 ; 54.762,13.032 cw(c54.456,13.032) 54.673,12.815 ccw(c54.456,13.032) 54.762,13.032 ; 54.762,13.032 ccw(c55.069,13.032) 54.852,12.815 cw(c55.069,13.032) 54.762,13.032 ; 66.294,13.032 cw(c65.987,13.032) 66.204,12.815 ccw(c65.987,13.032) 66.294,13.032 ; 66.294,13.032 ccw(c66.601,13.032) 66.384,12.815 cw(c66.601,13.032) 66.294,13.032 ; 79.248,65.733 cw(c79.555,65.733) 79.338,65.95 ccw(c79.555,65.733) 79.248,65.733 ; 79.248,65.733 ccw(c78.941,65.733) 79.158,65.95 cw(c78.941,65.733) 79.248,65.733
PA6: P1.33 U1.31 U6.2 | length 156.6
  Top Layer w0.254: P1.33@15.24,33.02 16.561,34.341 34.573,34.341 U1.31@37.696,37.464 39.145,38.913 v1@49.886,38.913 ; v1(54.153,13.437) v1(65.278,13.437) ; U6.2@76.683,67.308 78.662,67.308 v1(78.664,67.31) ; 15.87,33.65 cw(c15.24,34.28) 15.24,33.389 ccw(c15.24,34.28) 15.87,33.65 ; 15.87,33.65 ccw(c16.5,33.02) 15.609,33.02 cw(c16.5,33.02) 15.87,33.65 ; 16.304,34.084 cw(c15.24,35.147) 15.24,33.643 ccw(c15.24,35.147) 16.304,34.084 ; 16.304,34.084 ccw(c17.367,33.02) 15.863,33.02 cw(c17.367,33.02) 16.304,34.084 ; 49.604,38.913 cw(c49.604,38.606) 49.821,38.823 ccw(c49.604,38.606) 49.604,38.913 ; 49.604,38.913 ccw(c49.604,39.219) 49.821,39.003 cw(c49.604,39.219) 49.604,38.913 ; 54.459,13.437 cw(c54.459,13.743) 54.243,13.526 ccw(c54.459,13.743) 54.459,13.437 ; 54.459,13.437 ccw(c54.459,13.13) 54.243,13.347 cw(c54.459,13.13) 54.459,13.437 ; 64.971,13.437 cw(c64.971,13.13) 65.188,13.347 ccw(c64.971,13.13) 64.971,13.437 ; 64.971,13.437 ccw(c64.971,13.743) 65.188,13.526 cw(c64.971,13.743) 64.971,13.437 ; 77.823,67.308 cw(c77.823,67.738) 77.52,67.434 ccw(c77.823,67.738) 77.823,67.308 ; 77.823,67.308 ccw(c77.823,66.879) 77.52,67.183 cw(c77.823,66.879) 77.823,67.308 ; 78.353,67.308 ccw(c78.353,67.621) 78.574,67.4 cw(c78.353,67.621) 78.353,67.308 ; 78.361,67.308 cw(c78.361,67.007) 78.574,67.22 ccw(c78.361,67.007) 78.361,67.308
  Bottom Layer w0.254: v1(49.911,38.913) 50.8,38.913 54.153,35.56 v1(54.153,13.437) ; v1(65.278,13.437) 65.278,26.568 67.92,29.21 67.92,53.899 68.656,54.635 73.228,54.635 73.812,55.22 73.812,60.249 78.664,65.1 v1(78.664,67.31) ; 50.218,38.913 cw(c50.218,39.219) 50.001,39.003 ccw(c50.218,39.219) 50.218,38.913 ; 50.218,38.913 ccw(c50.218,38.606) 50.001,38.823 cw(c50.218,38.606) 50.218,38.913 ; 54.153,13.743 cw(c53.846,13.743) 54.063,13.526 ccw(c53.846,13.743) 54.153,13.743 ; 54.153,13.743 ccw(c54.459,13.743) 54.243,13.526 cw(c54.459,13.743) 54.153,13.743 ; 65.278,13.743 cw(c64.971,13.743) 65.188,13.526 ccw(c64.971,13.743) 65.278,13.743 ; 65.278,13.743 ccw(c65.585,13.743) 65.368,13.526 cw(c65.585,13.743) 65.278,13.743 ; 78.664,67.003 cw(c78.97,67.003) 78.754,67.22 ccw(c78.97,67.003) 78.664,67.003 ; 78.664,67.003 ccw(c78.357,67.003) 78.574,67.22 cw(c78.357,67.003) 78.664,67.003
PA9: P2.32 U1.68 U10.3 | length 74.8
  Top Layer w0.254: U1.68@52.58,36.757 54.107,35.23 68.072,35.23 69.647,36.805 71.399,36.805 P2.32@72.644,35.56 74.041,35.56 ; U10.3@78.502,13.411 v1(80.95,13.411) ; v1(80.95,35.992) 74.473,35.992 74.041,35.56 ; 71.58,36.624 cw(c70.517,35.56) 72.021,35.56 ccw(c70.517,35.56) 71.58,36.624 ; 71.58,36.624 ccw(c72.644,37.687) 72.644,36.183 cw(c72.644,37.687) 71.58,36.624 ; 72.014,36.19 cw(c71.384,35.56) 72.275,35.56 ccw(c71.384,35.56) 72.014,36.19 ; 72.014,36.19 ccw(c72.644,36.82) 72.644,35.929 cw(c72.644,36.82) 72.014,36.19 ; 73.471,35.56 cw(c73.471,36.303) 72.919,35.807 ccw(c73.471,36.303) 73.471,35.56 ; 73.471,35.56 ccw(c73.471,34.817) 72.919,35.313 cw(c73.471,34.817) 73.471,35.56 ; 74.041,35.56 cw(c74.041,36.815) 73.108,35.976 ccw(c74.041,36.815) 74.041,35.56 ; 74.041,35.56 ccw(c74.041,34.305) 73.108,35.144 cw(c74.041,34.305) 74.041,35.56 ; 79.72,13.411 cw(c79.72,13.829) 79.425,13.534 ccw(c79.72,13.829) 79.72,13.411 ; 79.72,13.411 ccw(c79.72,12.994) 79.425,13.289 cw(c79.72,12.994) 79.72,13.411 ; 80.643,13.411 cw(c80.643,13.105) 80.86,13.321 ccw(c80.643,13.105) 80.643,13.411 ; 80.643,13.411 ccw(c80.643,13.718) 80.86,13.501 cw(c80.643,13.718) 80.643,13.411 ; 80.643,35.992 cw(c80.643,35.685) 80.86,35.902 ccw(c80.643,35.685) 80.643,35.992 ; 80.643,35.992 ccw(c80.643,36.298) 80.86,36.082 cw(c80.643,36.298) 80.643,35.992 ; v1(80.95,13.411) 80.924,13.386 v1(80.95,13.411)
  Bottom Layer w0.254: v1(80.95,13.411) v1(80.95,35.992) ; 80.95,13.718 cw(c80.643,13.718) 80.86,13.501 ccw(c80.643,13.718) 80.95,13.718 ; 80.95,13.718 ccw(c81.256,13.718) 81.04,13.501 cw(c81.256,13.718) 80.95,13.718 ; 80.95,35.685 cw(c81.256,35.685) 81.04,35.902 ccw(c81.256,35.685) 80.95,35.685 ; 80.95,35.685 ccw(c80.643,35.685) 80.86,35.902 cw(c80.643,35.685) 80.95,35.685
PA10: P2.29 U1.69 U10.2 | length 75.1
  Top Layer w0.254: U1.69@52.934,37.11 54.357,35.687 67.624,35.687 70.037,38.1 P2.29@70.104,38.1 ; v1(73.914,36.881) v1@79.477,36.881 ; U10.2@78.502,14.681 v1(80.289,14.681) ; 74.221,36.881 cw(c74.221,37.187) 74.004,36.971 ccw(c74.221,37.187) 74.221,36.881 ; 74.221,36.881 ccw(c74.221,36.574) 74.004,36.791 cw(c74.221,36.574) 74.221,36.881 ; 79.145,36.881 cw(c79.145,36.574) 79.361,36.791 ccw(c79.145,36.574) 79.145,36.881 ; 79.145,36.881 ccw(c79.145,37.187) 79.361,36.971 cw(c79.145,37.187) 79.145,36.881 ; 79.72,14.681 cw(c79.72,15.099) 79.425,14.804 ccw(c79.72,15.099) 79.72,14.681 ; 79.72,14.681 ccw(c79.72,14.264) 79.425,14.559 cw(c79.72,14.264) 79.72,14.681 ; 79.983,14.681 cw(c79.983,14.375) 80.2,14.591 ccw(c79.983,14.375) 79.983,14.681 ; 79.983,14.681 ccw(c79.983,14.988) 80.2,14.771 cw(c79.983,14.988) 79.983,14.681 ; 68.927,36.989 cw(c70.104,35.812) 70.104,37.477 ccw(c70.104,35.812) 68.927,36.989 ; 69.088,37.15 ccw(c68.138,38.1) 69.481,38.1 cw(c68.138,38.1) 69.088,37.15 ; 69.36,37.423 cw(c70.104,36.679) 70.104,37.731 ccw(c70.104,36.679) 69.36,37.423 ; 69.521,37.584 ccw(c69.005,38.1) 69.735,38.1 cw(c69.005,38.1) 69.521,37.584
  Bottom Layer w0.254: P2.29@70.104,38.1 71.323,36.881 v1(73.914,36.881) ; v1(79.451,36.881) 80.289,36.043 v1(80.289,14.681) ; 70.734,37.47 cw(c71.364,38.1) 70.473,38.1 ccw(c71.364,38.1) 70.734,37.47 ; 70.734,37.47 ccw(c70.104,36.84) 70.104,37.731 cw(c70.104,36.84) 70.734,37.47 ; 71.168,37.036 cw(c72.231,38.1) 70.727,38.1 ccw(c72.231,38.1) 71.168,37.036 ; 71.168,37.036 ccw(c70.104,35.973) 70.104,37.477 cw(c70.104,35.973) 71.168,37.036 ; 73.607,36.881 cw(c73.607,36.574) 73.824,36.791 ccw(c73.607,36.574) 73.607,36.881 ; 73.607,36.881 ccw(c73.607,37.187) 73.824,36.971 cw(c73.607,37.187) 73.607,36.881 ; 79.668,36.664 cw(c79.885,36.881) 79.578,36.881 ccw(c79.885,36.881) 79.668,36.664 ; 79.668,36.664 ccw(c79.451,36.447) 79.451,36.754 cw(c79.451,36.447) 79.668,36.664 ; 80.289,14.988 cw(c79.983,14.988) 80.2,14.771 ccw(c79.983,14.988) 80.289,14.988 ; 80.289,14.988 ccw(c80.596,14.988) 80.379,14.771 cw(c80.596,14.988) 80.289,14.988
PA13: JTAG.7 P2.28 R2.2 U1.72 | length 140.4
  Top Layer w0.254: v1(21.92,91.467) 22.506,90.881 36.5,90.881 v1(37.567,89.814) 37.643,89.738 v1(37.643,82.118) ; v1(44.018,61.265) 59.944,61.265 v1(60.96,60.249) ; U1.72@53.994,38.171 55.183,36.982 59.741,36.982 v1(64.668,41.91) 71.374,41.91 P2.28@72.644,40.64 ; 22.137,91.25 cw(c22.354,91.467) 22.047,91.467 ccw(c22.354,91.467) 22.137,91.25 ; 22.137,91.25 ccw(c21.92,91.033) 21.92,91.34 cw(c21.92,91.033) 22.137,91.25 ; 37.35,90.031 cw(c37.133,89.814) 37.44,89.814 ccw(c37.133,89.814) 37.35,90.031 ; 37.35,90.031 ccw(c37.567,90.248) 37.567,89.941 cw(c37.567,90.248) 37.35,90.031 ; 37.643,82.425 cw(c37.336,82.425) 37.553,82.208 ccw(c37.336,82.425) 37.643,82.425 ; 37.643,82.425 ccw(c37.949,82.425) 37.733,82.208 cw(c37.949,82.425) 37.643,82.425 ; 44.325,61.265 cw(c44.325,61.571) 44.108,61.355 ccw(c44.325,61.571) 44.325,61.265 ; 44.325,61.265 ccw(c44.325,60.958) 44.108,61.175 cw(c44.325,60.958) 44.325,61.265 ; 60.743,60.466 cw(c60.526,60.249) 60.833,60.249 ccw(c60.526,60.249) 60.743,60.466 ; 60.743,60.466 ccw(c60.96,60.682) 60.96,60.376 cw(c60.96,60.682) 60.743,60.466 ; 64.452,41.693 cw(c64.668,41.476) 64.668,41.783 ccw(c64.668,41.476) 64.452,41.693 ; 64.452,41.693 ccw(c64.235,41.91) 64.541,41.91 cw(c64.235,41.91) 64.452,41.693 ; 64.975,41.91 cw(c64.975,42.217) 64.758,42 ccw(c64.975,42.217) 64.975,41.91 ; 64.975,41.91 ccw(c64.975,41.603) 64.758,41.82 cw(c64.975,41.603) 64.975,41.91 ; 71.58,41.704 cw(c70.517,40.64) 72.021,40.64 ccw(c70.517,40.64) 71.58,41.704 ; 71.58,41.704 ccw(c72.644,42.767) 72.644,41.263 cw(c72.644,42.767) 71.58,41.704 ; 72.014,41.27 cw(c71.384,40.64) 72.275,40.64 ccw(c71.384,40.64) 72.014,41.27 ; 72.014,41.27 ccw(c72.644,41.9) 72.644,41.009 cw(c72.644,41.9) 72.014,41.27 ; v1@37.477,89.725 cw(c37.076,89.324) 37.643,89.324 ccw(c37.076,89.324) v1@37.477,89.725
  Bottom Layer w0.254: v1(21.92,91.467) JTAG.7@21.92,94.056 ; v1@37.643,82.093 37.643,76.073 44.018,69.698 v1(44.018,61.265) ; v1(60.96,60.249) 64.668,56.54 v1(64.668,41.91) ; R2.2@21.92,91.774 cw(c21.614,91.774) 21.83,91.557 ccw(c21.614,91.774) R2.2@21.92,91.774 ; R2.2@21.92,91.774 ccw(c22.227,91.774) 22.01,91.557 cw(c22.227,91.774) R2.2@21.92,91.774 ; 21.92,92.515 cw(c23.424,92.515) 22.361,93.578 ccw(c23.424,92.515) 21.92,92.515 ; 21.92,92.515 ccw(c20.416,92.515) 21.48,93.578 cw(c20.416,92.515) 21.92,92.515 ; 21.92,92.693 cw(c20.694,92.693) 21.561,91.826 ccw(c20.694,92.693) 21.92,92.693 ; 21.92,92.693 ccw(c23.147,92.693) 22.279,91.826 cw(c23.147,92.693) 21.92,92.693 ; 21.92,93.128 cw(c22.811,93.128) 22.181,93.758 ccw(c22.811,93.128) 21.92,93.128 ; 21.92,93.128 ccw(c21.029,93.128) 21.659,93.758 cw(c21.029,93.128) 21.92,93.128 ; 37.643,81.812 cw(c37.949,81.812) 37.733,82.028 ccw(c37.949,81.812) 37.643,81.812 ; 37.643,81.812 ccw(c37.336,81.812) 37.553,82.028 cw(c37.336,81.812) 37.643,81.812 ; 44.018,61.571 cw(c43.712,61.571) 43.928,61.355 ccw(c43.712,61.571) 44.018,61.571 ; 44.018,61.571 ccw(c44.325,61.571) 44.108,61.355 cw(c44.325,61.571) 44.018,61.571 ; 61.177,60.032 cw(c61.394,60.249) 61.087,60.249 ccw(c61.394,60.249) 61.177,60.032 ; 61.177,60.032 ccw(c60.96,59.815) 60.96,60.122 cw(c60.96,59.815) 61.177,60.032 ; 64.668,42.217 cw(c64.362,42.217) 64.579,42 ccw(c64.362,42.217) 64.668,42.217 ; 64.668,42.217 ccw(c64.975,42.217) 64.758,42 cw(c64.975,42.217) 64.668,42.217
PA14: JTAG.9 P2.25 R3.1 U1.76 | length 131.6
  Top Layer w0.254: v1(24.46,91.467) 37.082,91.467 v1(38.379,90.17) v1(38.379,82.626) ; v1(44.78,61.925) 60.376,61.925 v1(61.493,60.808) ; U1.76@55.055,41.388 56.847,43.18 v1(65.329,43.18) P2.25@70.104,43.18 ; 24.767,91.467 cw(c24.767,91.774) 24.55,91.557 ccw(c24.767,91.774) 24.767,91.467 ; 24.767,91.467 ccw(c24.767,91.16) 24.55,91.377 cw(c24.767,91.16) 24.767,91.467 ; 38.163,90.387 cw(c37.946,90.17) 38.252,90.17 ccw(c37.946,90.17) 38.163,90.387 ; 38.163,90.387 ccw(c38.379,90.604) 38.379,90.297 cw(c38.379,90.604) 38.163,90.387 ; 38.379,82.933 cw(c38.073,82.933) 38.29,82.716 ccw(c38.073,82.933) 38.379,82.933 ; 38.379,82.933 ccw(c38.686,82.933) 38.469,82.716 cw(c38.686,82.933) 38.379,82.933 ; 38.379,89.863 cw(c38.686,89.863) 38.469,90.08 ccw(c38.686,89.863) 38.379,89.863 ; 38.379,89.863 ccw(c38.073,89.863) 38.29,90.08 cw(c38.073,89.863) 38.379,89.863 ; 45.087,61.925 cw(c45.087,62.232) 44.87,62.015 ccw(c45.087,62.232) 45.087,61.925 ; 45.087,61.925 ccw(c45.087,61.619) 44.87,61.835 cw(c45.087,61.619) 45.087,61.925 ; 61.277,61.024 cw(c61.06,60.808) 61.366,60.808 ccw(c61.06,60.808) 61.277,61.024 ; 61.277,61.024 ccw(c61.493,61.241) 61.493,60.935 cw(c61.493,61.241) 61.277,61.024 ; 65.022,43.18 cw(c65.022,42.873) 65.239,43.09 ccw(c65.022,42.873) 65.022,43.18 ; 65.022,43.18 ccw(c65.022,43.487) 65.239,43.27 cw(c65.022,43.487) 65.022,43.18 ; 65.635,43.18 cw(c65.635,43.487) 65.419,43.27 ccw(c65.635,43.487) 65.635,43.18 ; 65.635,43.18 ccw(c65.635,42.873) 65.419,43.09 cw(c65.635,42.873) 65.635,43.18 ; 68.6,43.18 cw(c68.6,41.676) 69.663,42.739 ccw(c68.6,41.676) 68.6,43.18 ; 68.6,43.18 ccw(c68.6,44.684) 69.663,43.621 cw(c68.6,44.684) 68.6,43.18 ; 69.213,43.18 cw(c69.213,42.289) 69.843,42.919 ccw(c69.213,42.289) 69.213,43.18 ; 69.213,43.18 ccw(c69.213,44.071) 69.843,43.441 cw(c69.213,44.071) 69.213,43.18
  Bottom Layer w0.254: v1(24.46,91.467) JTAG.9@24.46,94.056 ; v1(38.379,82.626) 38.379,76.556 44.78,70.155 v1(44.78,61.925) ; v1(61.493,60.808) 61.519,60.808 65.329,56.998 v1(65.329,43.18) ; R3.1@24.46,91.774 cw(c24.154,91.774) 24.37,91.557 ccw(c24.154,91.774) R3.1@24.46,91.774 ; R3.1@24.46,91.774 ccw(c24.767,91.774) 24.55,91.557 cw(c24.767,91.774) R3.1@24.46,91.774 ; 24.46,92.515 cw(c25.964,92.515) 24.901,93.578 ccw(c25.964,92.515) 24.46,92.515 ; 24.46,92.515 ccw(c22.956,92.515) 24.02,93.578 cw(c22.956,92.515) 24.46,92.515 ; 24.46,92.693 cw(c23.234,92.693) 24.101,91.826 ccw(c23.234,92.693) 24.46,92.693 ; 24.46,92.693 ccw(c25.687,92.693) 24.819,91.826 cw(c25.687,92.693) 24.46,92.693 ; 24.46,93.128 cw(c25.351,93.128) 24.721,93.758 ccw(c25.351,93.128) 24.46,93.128 ; 24.46,93.128 ccw(c23.569,93.128) 24.199,93.758 cw(c23.569,93.128) 24.46,93.128 ; 38.379,82.32 cw(c38.686,82.32) 38.469,82.536 ccw(c38.686,82.32) 38.379,82.32 ; 38.379,82.32 ccw(c38.073,82.32) 38.29,82.536 cw(c38.073,82.32) 38.379,82.32 ; 44.78,62.232 cw(c44.474,62.232) 44.69,62.015 ccw(c44.474,62.232) 44.78,62.232 ; 44.78,62.232 ccw(c45.087,62.232) 44.87,62.015 cw(c45.087,62.232) 44.78,62.232 ; 65.329,43.487 cw(c65.022,43.487) 65.239,43.27 ccw(c65.022,43.487) 65.329,43.487 ; 65.329,43.487 ccw(c65.635,43.487) 65.419,43.27 cw(c65.635,43.487) 65.329,43.487 ; v1@61.493,60.681 cw(c61.493,60.313) 61.754,60.573 ccw(c61.493,60.313) v1@61.493,60.681 ; v1@61.62,60.808 ccw(c61.866,60.808) 61.692,60.634 cw(c61.866,60.808) v1@61.62,60.808
PA15: P2.26 U1.77 | length 27.1
  Top Layer w0.254: U1.77@54.701,41.742 57.435,44.475 71.349,44.475 P2.26@72.644,43.18 ; 71.58,44.244 cw(c70.517,43.18) 72.021,43.18 ccw(c70.517,43.18) 71.58,44.244 ; 71.58,44.244 ccw(c72.644,45.307) 72.644,43.803 cw(c72.644,45.307) 71.58,44.244 ; 72.014,43.81 cw(c71.384,43.18) 72.275,43.18 ccw(c71.384,43.18) 72.014,43.81 ; 72.014,43.81 ccw(c72.644,44.44) 72.644,43.549 cw(c72.644,44.44) 72.014,43.81
PB0: 2.4'/2.8'LCD.34 P1.37 U1.35 | length 71.8
  Top Layer w0.254: P1.37@15.24,27.94 16.535,29.235 32.296,29.235 U1.35@39.11,36.049 ; 15.87,28.57 cw(c15.24,29.2) 15.24,28.309 ccw(c15.24,29.2) 15.87,28.57 ; 15.87,28.57 ccw(c16.5,27.94) 15.609,27.94 cw(c16.5,27.94) 15.87,28.57 ; 16.304,29.004 cw(c15.24,30.067) 15.24,28.563 ccw(c15.24,30.067) 16.304,29.004 ; 16.304,29.004 ccw(c17.367,27.94) 15.863,27.94 cw(c17.367,27.94) 16.304,29.004 ; 24.611,29.235 cw(c24.611,28.929) 24.828,29.146 ccw(c24.611,28.929) 24.611,29.235 ; 24.611,29.235 ccw(c24.611,29.542) 24.828,29.325 cw(c24.611,29.542) 24.611,29.235 ; 25.224,29.235 cw(c25.224,29.542) 25.007,29.325 ccw(c25.224,29.542) 25.224,29.235 ; 25.224,29.235 ccw(c25.224,28.929) 25.007,29.146 cw(c25.224,28.929) 25.224,29.235
  Bottom Layer w0.254: 2.4'/2.8'LCD.34@23.647,3.734 24.917,5.004 v1(24.917,29.235) ; 24.341,4.428 cw(c23.647,5.121) 23.647,4.14 ccw(c23.647,5.121) 24.341,4.428 ; 24.341,4.428 ccw(c25.035,3.734) 24.054,3.734 cw(c25.035,3.734) 24.341,4.428 ; 24.775,4.861 cw(c23.647,5.989) 23.647,4.394 ccw(c23.647,5.989) 24.775,4.861 ; 24.775,4.861 ccw(c25.902,3.734) 24.308,3.734 cw(c25.902,3.734) 24.775,4.861 ; 24.917,28.929 cw(c25.224,28.929) 25.007,29.146 ccw(c25.224,28.929) 24.917,28.929 ; 24.917,28.929 ccw(c24.611,28.929) 24.828,29.146 cw(c24.611,28.929) 24.917,28.929
PB1: 2.4'/2.8'LCD.31 P1.38 U1.36 | length 64.4
  Top Layer w0.254: P1.38@17.78,27.94 31.707,27.94 U1.36@39.463,35.696 ; 18.671,27.94 cw(c18.671,28.831) 18.041,28.201 ccw(c18.671,28.831) 18.671,27.94 ; 18.671,27.94 ccw(c18.671,27.049) 18.041,27.679 cw(c18.671,27.049) 18.671,27.94 ; 19.284,27.94 cw(c19.284,29.444) 18.221,28.381 ccw(c19.284,29.444) 19.284,27.94 ; 19.284,27.94 ccw(c19.284,26.436) 18.221,27.499 cw(c19.284,26.436) 19.284,27.94 ; 25.819,27.94 cw(c25.819,27.547) 26.098,27.825 ccw(c25.819,27.547) 25.819,27.94 ; v1@26.277,27.825 cw(c26.555,27.547) 26.555,27.94 ccw(c26.555,27.547) v1@26.277,27.825
  Bottom Layer w0.254: 2.4'/2.8'LCD.31@26.187,6.274 v1(26.187,27.915) ; 26.187,7.255 cw(c25.206,7.255) 25.9,6.561 ccw(c25.206,7.255) 26.187,7.255 ; 26.187,7.255 ccw(c27.169,7.255) 26.475,6.561 cw(c27.169,7.255) 26.187,7.255 ; 26.187,7.868 cw(c24.593,7.868) 25.72,6.741 ccw(c24.593,7.868) 26.187,7.868 ; 26.187,7.868 ccw(c27.782,7.868) 26.654,6.741 cw(c27.782,7.868) 26.187,7.868 ; 26.187,27.608 cw(c26.494,27.608) 26.277,27.825 ccw(c26.494,27.608) 26.187,27.608 ; 26.187,27.608 ccw(c25.881,27.608) 26.098,27.825 cw(c25.881,27.608) 26.187,27.608
PB3: P2.14 U1.89 | length 35.9
  Top Layer w0.254: U1.89@50.459,45.984 64.165,59.69 71.374,59.69 P2.14@72.644,58.42 ; 71.58,59.484 cw(c70.517,58.42) 72.021,58.42 ccw(c70.517,58.42) 71.58,59.484 ; 71.58,59.484 ccw(c72.644,60.547) 72.644,59.043 cw(c72.644,60.547) 71.58,59.484 ; 72.014,59.05 cw(c71.384,58.42) 72.275,58.42 ccw(c71.384,58.42) 72.014,59.05 ; 72.014,59.05 ccw(c72.644,59.68) 72.644,58.789 cw(c72.644,59.68) 72.014,59.05
PB4: P2.11 U1.90 | length 33.6
  Top Layer w0.254: U1.90@50.105,46.338 64.727,60.96 P2.11@70.104,60.96 ; 68.6,60.96 cw(c68.6,59.456) 69.663,60.519 ccw(c68.6,59.456) 68.6,60.96 ; 68.6,60.96 ccw(c68.6,62.464) 69.663,61.401 cw(c68.6,62.464) 68.6,60.96 ; 69.213,60.96 cw(c69.213,60.069) 69.843,60.699 ccw(c69.213,60.069) 69.213,60.96 ; 69.213,60.96 ccw(c69.213,61.851) 69.843,61.221 cw(c69.213,61.851) 69.213,60.96
PB5: P2.12 U1.91 U6.5 | length 58.7
  Top Layer w0.254: U1.91@49.752,46.691 65.29,62.23 71.374,62.23 P2.12@72.644,60.96 77.47,60.96 81.28,64.77 U6.5@83.541,64.77 ; 71.58,62.024 cw(c70.517,60.96) 72.021,60.96 ccw(c70.517,60.96) 71.58,62.024 ; 71.58,62.024 ccw(c72.644,63.087) 72.644,61.583 cw(c72.644,63.087) 71.58,62.024 ; 72.014,61.59 cw(c71.384,60.96) 72.275,60.96 ccw(c71.384,60.96) 72.014,61.59 ; 72.014,61.59 ccw(c72.644,62.22) 72.644,61.329 cw(c72.644,62.22) 72.014,61.59 ; 73.535,60.96 cw(c73.535,61.851) 72.905,61.221 ccw(c73.535,61.851) 73.535,60.96 ; 73.535,60.96 ccw(c73.535,60.069) 72.905,60.699 cw(c73.535,60.069) 73.535,60.96 ; 74.148,60.96 cw(c74.148,62.464) 73.085,61.401 ccw(c74.148,62.464) 74.148,60.96 ; 74.148,60.96 ccw(c74.148,59.456) 73.085,60.519 cw(c74.148,59.456) 74.148,60.96 ; 82.4,64.77 cw(c82.4,64.341) 82.704,64.644 ccw(c82.4,64.341) 82.4,64.77 ; 82.4,64.77 ccw(c82.4,65.199) 82.704,64.896 cw(c82.4,65.199) 82.4,64.77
